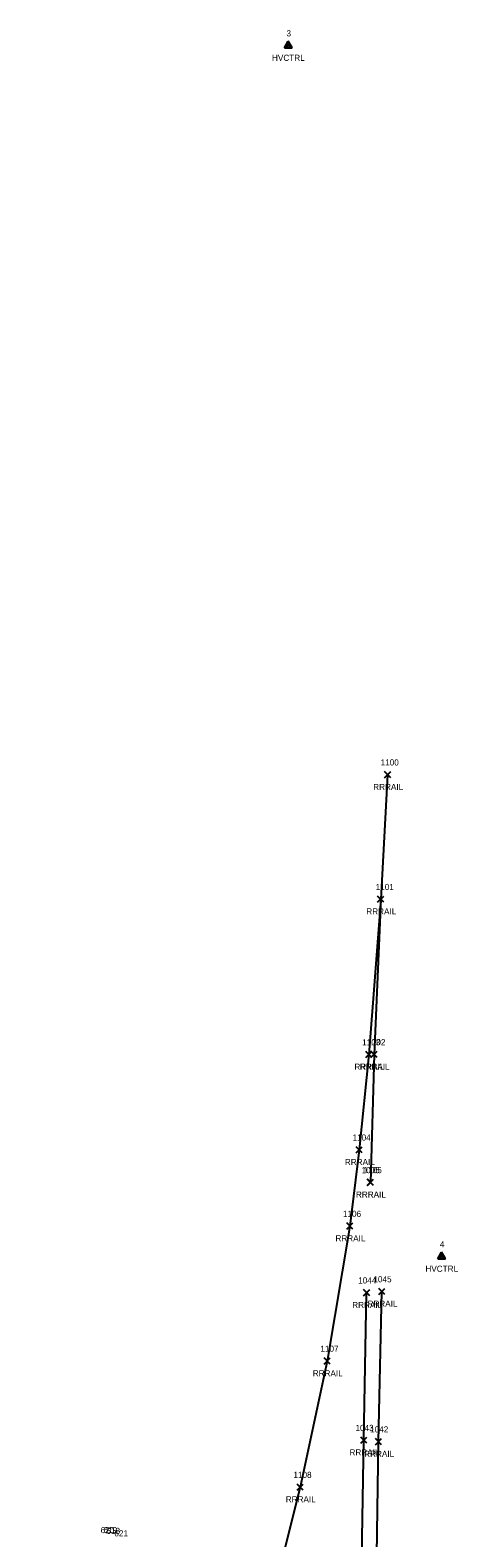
# Model space of a CAD drawing. Extents: x 1764889 to 1767296, y 695936 to 698960.
# Drawn here: x 1766299.9 to 1766439.7, y 696718.8 to 697211.7 of the extents above; entities that cross this region are included whole.
import ezdxf

# ---------------------------------------------------------------- set-up
doc = ezdxf.new("R2010")
doc.units = 0
for name, color, linetype in [('C_A', 7, 'Continuous'), ('C_I', 7, 'Continuous'), ('CPSM', 7, 'Continuous'), ('L_I', 7, 'Continuous'), ('P_I', 7, 'Continuous'), ('R_A', 7, 'Continuous'), ('R_I', 7, 'Continuous'), ('R_TIC', 7, 'Continuous'), ('RR', 7, 'Continuous')]:
    doc.layers.add(name, color=color, linetype=linetype)

msp = doc.modelspace()

# ---------------------------------------------------------------- linework, layer by layer
at = {"layer": 'CPSM'}
for p, q in [((1766383.02, 697205.93), (1766384.27, 697208.09)), ((1766383.02, 697205.93), (1766384.27, 697208.09)), ((1766383.02, 697205.93), (1766384.27, 697208.09)), ((1766383.02, 697205.93), (1766384.27, 697208.09)), ((1766385.52, 697205.93), (1766384.27, 697208.09)), ((1766384.27, 697206.65), (1766384.27, 697208.09)), ((1766385.52, 697205.93), (1766384.27, 697208.09)), ((1766384.27, 697206.65), (1766384.27, 697208.09)), ((1766385.52, 697205.93), (1766384.27, 697208.09)), ((1766384.27, 697206.65), (1766384.27, 697208.09)), ((1766385.52, 697205.93), (1766384.27, 697208.09)), ((1766384.27, 697206.65), (1766384.27, 697208.09)), ((1766383.02, 697205.93), (1766384.27, 697206.65)), ((1766383.02, 697205.93), (1766384.27, 697206.65)), ((1766383.02, 697205.93), (1766384.27, 697206.65)), ((1766383.02, 697205.93), (1766384.27, 697206.65)), ((1766383.02, 697205.93), (1766385.52, 697205.93)), ((1766383.02, 697205.93), (1766385.52, 697205.93)), ((1766383.02, 697205.93), (1766385.52, 697205.93)), ((1766383.02, 697205.93), (1766385.52, 697205.93)), ((1766384.27, 697206.65), (1766384.27, 697206.65)), ((1766384.27, 697206.65), (1766385.52, 697205.93)), ((1766384.27, 697206.65), (1766384.27, 697206.65)), ((1766384.27, 697206.65), (1766385.52, 697205.93)), ((1766384.27, 697206.65), (1766384.27, 697206.65)), ((1766384.27, 697206.65), (1766385.52, 697205.93)), ((1766384.27, 697206.65), (1766384.27, 697206.65)), ((1766384.27, 697206.65), (1766385.52, 697205.93)), ((1766433.19, 696810.09), (1766434.44, 696812.25)), ((1766433.19, 696810.09), (1766434.44, 696812.25)), ((1766433.19, 696810.09), (1766434.44, 696812.25)), ((1766433.19, 696810.09), (1766434.44, 696812.25)), ((1766433.19, 696810.09), (1766434.44, 696810.81)), ((1766433.19, 696810.09), (1766434.44, 696810.81)), ((1766433.19, 696810.09), (1766434.44, 696810.81)), ((1766433.19, 696810.09), (1766434.44, 696810.81)), ((1766433.19, 696810.09), (1766435.69, 696810.09)), ((1766433.19, 696810.09), (1766435.69, 696810.09)), ((1766433.19, 696810.09), (1766435.69, 696810.09)), ((1766433.19, 696810.09), (1766435.69, 696810.09)), ((1766435.69, 696810.09), (1766434.44, 696812.25)), ((1766434.44, 696810.81), (1766434.44, 696812.25)), ((1766435.69, 696810.09), (1766434.44, 696812.25)), ((1766434.44, 696810.81), (1766434.44, 696812.25)), ((1766435.69, 696810.09), (1766434.44, 696812.25)), ((1766434.44, 696810.81), (1766434.44, 696812.25)), ((1766435.69, 696810.09), (1766434.44, 696812.25)), ((1766434.44, 696810.81), (1766434.44, 696812.25)), ((1766434.44, 696810.81), (1766434.44, 696810.81)), ((1766434.44, 696810.81), (1766435.69, 696810.09)), ((1766434.44, 696810.81), (1766434.44, 696810.81)), ((1766434.44, 696810.81), (1766435.69, 696810.09)), ((1766434.44, 696810.81), (1766434.44, 696810.81)), ((1766434.44, 696810.81), (1766435.69, 696810.09)), ((1766434.44, 696810.81), (1766434.44, 696810.81)), ((1766434.44, 696810.81), (1766435.69, 696810.09))]:
    msp.add_line(p, q, dxfattribs=at)
at = {"layer": 'R_TIC'}
for points in [[(1766415.77, 696967.31), (1766417.77, 696969.31)], [(1766417.77, 696967.31), (1766415.77, 696969.31)], [(1766413.51, 696926.61), (1766415.51, 696928.61)], [(1766415.51, 696926.61), (1766413.51, 696928.61)], [(1766413.51, 696926.61), (1766415.51, 696928.61)], [(1766415.51, 696926.61), (1766413.51, 696928.61)], [(1766409.63, 696875.83), (1766411.63, 696877.83)], [(1766411.63, 696875.83), (1766409.63, 696877.83)], [(1766411.32, 696875.89), (1766413.32, 696877.89)], [(1766413.32, 696875.89), (1766411.32, 696877.89)], [(1766406.5, 696844.7), (1766408.5, 696846.7)], [(1766408.5, 696844.7), (1766406.5, 696846.7)], [(1766410.1, 696834.04), (1766412.1, 696836.04)], [(1766412.1, 696834.04), (1766410.1, 696836.04)], [(1766410.14, 696834.05), (1766412.14, 696836.05)], [(1766412.14, 696834.05), (1766410.14, 696836.05)], [(1766403.42, 696819.76), (1766405.42, 696821.76)], [(1766405.42, 696819.76), (1766403.42, 696821.76)], [(1766408.91, 696797.98), (1766410.91, 696799.98)], [(1766410.91, 696797.98), (1766408.91, 696799.98)], [(1766413.9, 696798.38), (1766415.9, 696800.38)], [(1766415.9, 696798.38), (1766413.9, 696800.38)], [(1766395.99, 696775.65), (1766397.99, 696777.65)], [(1766397.99, 696775.65), (1766395.99, 696777.65)], [(1766408.02, 696749.78), (1766410.02, 696751.78)], [(1766410.02, 696749.78), (1766408.02, 696751.78)], [(1766412.82, 696749.29), (1766414.82, 696751.29)], [(1766414.82, 696749.29), (1766412.82, 696751.29)], [(1766387.17, 696734.44), (1766389.17, 696736.44)], [(1766389.17, 696734.44), (1766387.17, 696736.44)]]:
    msp.add_lwpolyline(points, dxfattribs=at)
at = {"layer": 'RR'}
for points in [[(1766416.77, 696968.31), (1766414.51, 696927.61), (1766412.32, 696876.89), (1766411.14, 696835.05)], [(1766414.51, 696927.61), (1766410.63, 696876.83), (1766407.5, 696845.7), (1766404.42, 696820.76), (1766396.99, 696776.65), (1766388.17, 696735.44), (1766377.78, 696694.21), (1766366.7, 696658.73), (1766355.14, 696628.57), (1766340.23, 696595.43), (1766321.37, 696561.38), (1766312.46, 696547.47), (1766299.86, 696528.94)], [(1766410.41, 696332.08), (1766409.46, 696420.45), (1766408.85, 696485.76), (1766408.53, 696550.3), (1766408.18, 696590.82), (1766408.03, 696642.92), (1766408.33, 696712.56), (1766409.02, 696750.78), (1766409.91, 696798.98)], [(1766415.4, 696332.21), (1766414.47, 696421.49), (1766413.91, 696486.12), (1766413.47, 696550.63), (1766413.06, 696590.68), (1766412.95, 696642.7), (1766413.23, 696713.18), (1766413.82, 696750.29), (1766414.9, 696799.38)]]:
    msp.add_lwpolyline(points, dxfattribs=at)

# ---------------------------------------------------------------- texts
at = {"layer": 'C_A'}
for p in [(1766378.96, 697201.65), (1766378.96, 697201.65), (1766378.96, 697201.65), (1766378.96, 697201.65), (1766429.13, 696805.81), (1766429.13, 696805.81), (1766429.13, 696805.81), (1766429.13, 696805.81)]:
    msp.add_text('HVCTRL', height=2, dxfattribs=at).set_placement(p)
at = {"layer": 'C_I'}
for s, p in [('3', (1766383.7, 697209.65)), ('3', (1766383.7, 697209.65)), ('3', (1766383.7, 697209.65)), ('3', (1766383.7, 697209.65)), ('4', (1766433.87, 696813.81)), ('4', (1766433.87, 696813.81)), ('4', (1766433.87, 696813.81)), ('4', (1766433.87, 696813.81))]:
    msp.add_text(s, height=2, dxfattribs=at).set_placement(p)
at = {"layer": 'L_I'}
msp.add_text('621', height=2, dxfattribs=at).set_placement((1766327.4, 696719.31))
at = {"layer": 'P_I'}
msp.add_text('620', height=2, dxfattribs=at).set_placement((1766322.91, 696720.37))
at = {"layer": 'R_A'}
for p in [(1766412.06, 696963.31), (1766409.8, 696922.61), (1766409.8, 696922.61), (1766405.92, 696871.83), (1766407.61, 696871.89), (1766402.79, 696840.7), (1766406.39, 696830.04), (1766406.43, 696830.05), (1766399.71, 696815.76), (1766405.2, 696793.98), (1766410.19, 696794.38), (1766392.28, 696771.65), (1766404.31, 696745.78), (1766409.11, 696745.29), (1766383.46, 696730.44)]:
    msp.add_text('RRRAIL', height=2, dxfattribs=at).set_placement(p)
at = {"layer": 'R_I'}
for s, p in [('1100', (1766414.48, 696971.31)), ('1101', (1766412.87, 696930.61)), ('1101', (1766412.87, 696930.61)), ('1103', (1766408.42, 696879.83)), ('1102', (1766410.12, 696879.89)), ('1104', (1766405.3, 696848.7)), ('1005', (1766408.25, 696838.04)), ('1105', (1766408.93, 696838.05)), ('1106', (1766402.16, 696823.76)), ('1044', (1766407.14, 696801.98)), ('1045', (1766412.12, 696802.38)), ('1107', (1766394.78, 696779.65)), ('1043', (1766406.25, 696753.78)), ('1042', (1766411.05, 696753.29)), ('1108', (1766385.96, 696738.44)), ('619', (1766323.84, 696720.4)), ('618', (1766324.81, 696720.11))]:
    msp.add_text(s, height=2, dxfattribs=at).set_placement(p)

doc.saveas('drawing.dxf')
